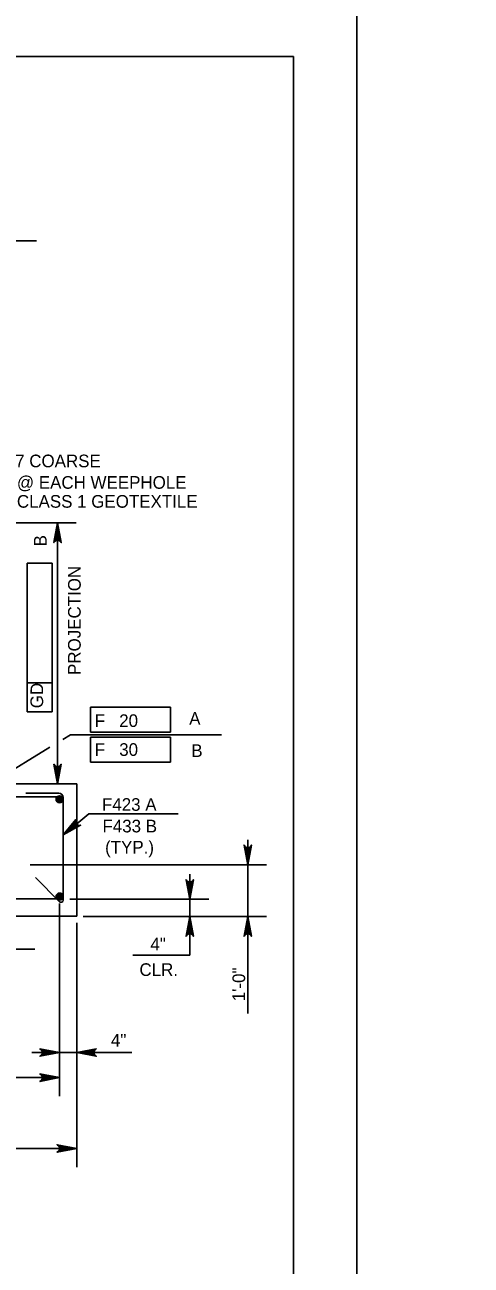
# Model space of a CAD drawing. Extents: x 638340 to 640242, y 295465 to 298435.
# Drawn here: x 639197.8 to 639303.6, y 296352.1 to 296646 of the extents above; entities that cross this region are included whole.
import ezdxf

# ---------------------------------------------------------------- set-up
doc = ezdxf.new("R2010")
doc.units = 0
for name, color, linetype in [('2', 7, 'Continuous'), ('Level 3', 7, 'Continuous'), ('Level 4', 7, 'Continuous'), ('Level 5', 7, 'Continuous'), ('Level 6', 7, 'Continuous'), ('Level 8', 7, 'Continuous'), ('Level 9', 7, 'Continuous'), ('PLT-BNDY', 7, 'Continuous')]:
    doc.layers.add(name, color=color, linetype=linetype)

msp = doc.modelspace()

# ---------------------------------------------------------------- linework, layer by layer
at = {"layer": '2'}
for p, q in [((638475.46, 296638.46), (639261.46, 296638.46)), ((639261.46, 296638.46), (639261.46, 296074.46))]:
    msp.add_line(p, q, dxfattribs=at)
at = {"layer": 'Level 3'}
for p, q in [((639164.96, 296594.81), (639200.6, 296594.81)), ((639250.64, 296449.91), (639250.64, 296452.85)), ((639199.1, 296446.96), (639255.06, 296446.96)), ((639250.64, 296446.96), (639250.64, 296434.69)), ((639236.89, 296441.77), (639236.89, 296444.77)), ((639208.44, 296438.78), (639241.38, 296438.78)), ((639236.89, 296438.78), (639236.89, 296434.69)), ((639211.63, 296434.69), (639255.06, 296434.69)), ((639211.65, 296434.69), (639241.38, 296434.69)), ((639236.89, 296431.69), (639236.89, 296425.53)), ((639250.64, 296431.74), (639250.64, 296411.75)), ((639236.89, 296425.53), (639223.38, 296425.53))]:
    msp.add_line(p, q, dxfattribs=at)
for points in [[(639250.64, 296446.96), (639249.77, 296451.61), (639250.01, 296451.25), (639250.33, 296451.07), (639250.64, 296451.02), (639250.95, 296451.07), (639251.26, 296451.25), (639251.51, 296451.61), (639250.64, 296446.96), (639251.26, 296451.25), (639250.95, 296451.07), (639250.64, 296446.96), (639250.64, 296451.02), (639250.33, 296451.07), (639250.64, 296446.96), (639250.01, 296451.25)], [(639236.89, 296438.78), (639236.02, 296443.43), (639236.27, 296443.07), (639236.58, 296442.89), (639236.89, 296442.83), (639237.2, 296442.89), (639237.51, 296443.07), (639237.76, 296443.43), (639236.89, 296438.78), (639237.51, 296443.07), (639237.2, 296442.89), (639236.89, 296438.78), (639236.89, 296442.83), (639236.58, 296442.89), (639236.89, 296438.78), (639236.27, 296443.07)], [(639236.89, 296434.69), (639237.76, 296430.04), (639237.51, 296430.39), (639237.2, 296430.58), (639236.89, 296430.63), (639236.58, 296430.58), (639236.27, 296430.39), (639236.02, 296430.04), (639236.89, 296434.69), (639236.27, 296430.39), (639236.58, 296430.58), (639236.89, 296434.69), (639236.89, 296430.63), (639237.2, 296430.58), (639236.89, 296434.69), (639237.51, 296430.39)], [(639250.64, 296434.69), (639251.51, 296430.04), (639251.26, 296430.39), (639250.95, 296430.58), (639250.64, 296430.63), (639250.33, 296430.58), (639250.01, 296430.39), (639249.77, 296430.04), (639250.64, 296434.69), (639250.01, 296430.39), (639250.33, 296430.58), (639250.64, 296434.69), (639250.64, 296430.63), (639250.95, 296430.58), (639250.64, 296434.69), (639251.26, 296430.39)]]:
    msp.add_lwpolyline(points, dxfattribs=at)
for points in [[(639250.15, 296449.91), (639251.13, 296449.91), (639250.64, 296446.96)], [(639236.39, 296441.77), (639237.39, 296441.77), (639236.89, 296438.78)], [(639236.39, 296431.69), (639237.39, 296431.69), (639236.89, 296434.69)], [(639250.15, 296431.74), (639251.13, 296431.74), (639250.64, 296434.69)]]:
    msp.add_lwpolyline(points, close=True, dxfattribs=at)
at = {"layer": 'Level 4'}
for p, q in [((639161.27, 296527.93), (639209.99, 296527.93)), ((639205.57, 296466.12), (639205.57, 296527.93)), ((639205.57, 296466.12), (639205.57, 296527.93)), ((639198.37, 296483.21), (639198.37, 296518.44)), ((639198.37, 296518.44), (639204.27, 296518.44)), ((639204.27, 296518.44), (639204.27, 296483.21)), ((639204.27, 296490.04), (639198.37, 296490.04)), ((639204.27, 296483.21), (639198.37, 296483.21)), ((639213.4, 296484.28), (639232.31, 296484.28)), ((639213.4, 296478.38), (639213.4, 296484.28)), ((639232.31, 296484.28), (639232.31, 296478.38)), ((639206.8, 296476.66), (639208.6, 296477.76)), ((639208.6, 296477.76), (639244.39, 296477.76)), ((639232.31, 296478.38), (639213.4, 296478.38)), ((639213.4, 296477.17), (639232.31, 296477.17)), ((639213.4, 296471.28), (639213.4, 296477.17)), ((639232.31, 296477.17), (639232.31, 296471.28)), ((639184.58, 296463.05), (639203.75, 296474.79)), ((639184.58, 296463.05), (639203.75, 296474.79)), ((639232.31, 296471.28), (639213.4, 296471.28)), ((639202.4, 296466.12), (639209.99, 296466.12)), ((639202.4, 296466.12), (639209.99, 296466.12)), ((639202.4, 296466.12), (639209.99, 296466.12)), ((639212.95, 296459.03), (639206.88, 296454.01)), ((639212.95, 296459.03), (639234.15, 296459.03)), ((639206.03, 296437.78), (639206.03, 296392.11)), ((639210.09, 296433.24), (639210.09, 296375.34)), ((639210.09, 296412.96), (639210.09, 296401.49)), ((639206.03, 296402.45), (639199.46, 296402.45)), ((639206.03, 296402.45), (639223.17, 296402.45)), ((639100.09, 296396.53), (639206.03, 296396.53)), ((639096.03, 296379.76), (639210.09, 296379.76))]:
    msp.add_line(p, q, dxfattribs=at)
for points in [[(639205.57, 296527.93), (639206.44, 296523.28), (639206.19, 296523.64), (639205.88, 296523.82), (639205.57, 296523.87), (639205.26, 296523.82), (639204.95, 296523.64), (639204.7, 296523.28), (639205.57, 296527.93), (639204.95, 296523.64), (639205.26, 296523.82), (639205.57, 296527.93), (639205.57, 296523.87), (639205.88, 296523.82), (639205.57, 296527.93), (639206.19, 296523.64)], [(639205.57, 296466.12), (639204.7, 296470.77), (639204.95, 296470.42), (639205.26, 296470.23), (639205.57, 296470.18), (639205.88, 296470.23), (639206.19, 296470.42), (639206.44, 296470.77), (639205.57, 296466.12), (639206.19, 296470.42), (639205.88, 296470.23), (639205.57, 296466.12), (639205.57, 296470.18), (639205.26, 296470.23), (639205.57, 296466.12), (639204.95, 296470.42)], [(639205.57, 296466.12), (639204.7, 296470.77), (639204.95, 296470.42), (639205.26, 296470.23), (639205.57, 296470.18), (639205.88, 296470.23), (639206.19, 296470.42), (639206.44, 296470.77), (639205.57, 296466.12), (639206.19, 296470.42), (639205.88, 296470.23), (639205.57, 296466.12), (639205.57, 296470.18), (639205.26, 296470.23), (639205.57, 296466.12), (639204.95, 296470.42)], [(639206.88, 296454.02), (639209.92, 296457.65), (639209.8, 296457.23), (639209.85, 296456.87), (639210.01, 296456.6), (639210.25, 296456.39), (639210.59, 296456.27), (639211.03, 296456.31), (639206.88, 296454.02), (639210.59, 296456.27), (639210.25, 296456.39), (639206.88, 296454.02), (639210.01, 296456.6), (639209.85, 296456.87), (639206.88, 296454.02), (639209.8, 296457.23)], [(639206.03, 296402.45), (639201.38, 296401.58), (639201.74, 296401.82), (639201.92, 296402.14), (639201.98, 296402.45), (639201.92, 296402.76), (639201.74, 296403.07), (639201.38, 296403.32), (639206.03, 296402.45), (639201.74, 296403.07), (639201.92, 296402.76), (639206.03, 296402.45), (639201.98, 296402.45), (639201.92, 296402.14), (639206.03, 296402.45), (639201.74, 296401.82)], [(639210.09, 296402.45), (639214.74, 296403.32), (639214.38, 296403.07), (639214.2, 296402.76), (639214.14, 296402.45), (639214.2, 296402.14), (639214.38, 296401.82), (639214.74, 296401.58), (639210.09, 296402.45), (639214.38, 296401.82), (639214.2, 296402.14), (639210.09, 296402.45), (639214.14, 296402.45), (639214.2, 296402.76), (639210.09, 296402.45), (639214.38, 296403.07)], [(639206.03, 296396.53), (639201.38, 296395.65), (639201.74, 296395.9), (639201.92, 296396.21), (639201.98, 296396.53), (639201.92, 296396.84), (639201.74, 296397.15), (639201.38, 296397.4), (639206.03, 296396.53), (639201.74, 296397.15), (639201.92, 296396.84), (639206.03, 296396.53), (639201.98, 296396.53), (639201.92, 296396.21), (639206.03, 296396.53), (639201.74, 296395.9)], [(639210.09, 296379.76), (639205.44, 296378.88), (639205.8, 296379.13), (639205.98, 296379.44), (639206.04, 296379.76), (639205.98, 296380.07), (639205.8, 296380.38), (639205.44, 296380.63), (639210.09, 296379.76), (639205.8, 296380.38), (639205.98, 296380.07), (639210.09, 296379.76), (639206.04, 296379.76), (639205.98, 296379.44), (639210.09, 296379.76), (639205.8, 296379.13)]]:
    msp.add_lwpolyline(points, dxfattribs=at)
for points in [[(639205.08, 296524.98), (639206.06, 296524.98), (639205.57, 296527.93)], [(639205.08, 296469.07), (639206.06, 296469.07), (639205.57, 296466.12)], [(639205.08, 296469.07), (639206.06, 296469.07), (639205.57, 296466.12)], [(639202.95, 296401.96), (639202.95, 296402.94), (639205.9, 296402.45)], [(639213.31, 296402.94), (639213.31, 296401.96), (639210.36, 296402.45)], [(639203.09, 296397.02), (639203.09, 296396.04), (639206.03, 296396.53)], [(639207.14, 296380.25), (639207.14, 296379.27), (639210.09, 296379.76)]]:
    msp.add_lwpolyline(points, close=True, dxfattribs=at)
at = {"layer": 'Level 5'}
for p, q in [((639206.1, 296466.11), (639206.1, 296466.11)), ((639206.1, 296466.11), (639206.1, 296466.11)), ((639209.85, 296466.11), (639209.85, 296466.11)), ((639209.85, 296466.11), (639209.85, 296466.11))]:
    msp.add_line(p, q, dxfattribs=at)
at = {"layer": 'Level 6'}
for p, q in [((639206.88, 296463.05), (639099.25, 296463.05)), ((639198.02, 296463.95), (639205.86, 296463.95)), ((639206.88, 296438.57), (639206.88, 296462.92)), ((639200.32, 296443.91), (639206.01, 296438.21)), ((639099.24, 296438.86), (639206.88, 296438.86))]:
    msp.add_line(p, q, dxfattribs=at)
for centre, radius in [((639206.03, 296462.48), 0.832), ((639206.03, 296462.48), 0.624), ((639206.03, 296462.48), 0.416), ((639206.03, 296462.48), 0.208), ((639206.03, 296439.44), 0.832), ((639206.03, 296439.44), 0.624), ((639206.03, 296439.44), 0.416), ((639206.03, 296439.44), 0.208)]:
    msp.add_circle(centre, radius, dxfattribs=at)
for centre, radius, start, end in [((639205.86, 296462.92), 1.02, 0, 90), ((639206.37, 296438.57), 0.511, 225, 0)]:
    msp.add_arc(centre, radius, start, end, dxfattribs=at)
at = {"layer": 'Level 8'}
msp.add_line((639200.19, 296426.97), (639194.06, 296426.97), dxfattribs=at)
at = {"layer": 'Level 9'}
for p, q in [((639210.09, 296466.12), (639156.55, 296466.12)), ((639210.09, 296466.12), (639156.55, 296466.12)), ((639210.09, 296466.12), (639156.55, 296466.12)), ((639210.09, 296434.77), (639210.09, 296466.12)), ((639096.03, 296434.77), (639210.09, 296434.77))]:
    msp.add_line(p, q, dxfattribs=at)
at = {"layer": 'PLT-BNDY'}
for points in [[(638435.46, 296653.46), (639276.46, 296653.46), (639276.46, 296059.46), (638435.46, 296059.46)], [(639276.46, 296653.46), (640117.46, 296653.46), (640117.46, 296059.46), (639276.46, 296059.46)]]:
    msp.add_lwpolyline(points, close=True, dxfattribs=at)

# ---------------------------------------------------------------- texts
at = {"layer": 'Level 3'}
for s, height, p in [('1/2 C.Y. NO. 57 COARSE', 3.0001, (639169.42, 296541.13)), ('4"', 3, (639227.55, 296426.66)), ('CLR.', 3, (639224.96, 296420.62)), ('4"', 3, (639218.2, 296403.9))]:
    msp.add_text(s, height=height, dxfattribs=at).set_placement(p)
msp.add_text('1\'-0"', height=3, rotation=90, dxfattribs=at).set_placement((639250, 296414.63))
at = {"layer": 'Level 4'}
for s, height, p in [('AGGREGATE @ EACH WEEPHOLE', 3.0001, (639169.4, 296536.04)), ('WRAPPED IN CLASS 1 GEOTEXTILE', 3.0001, (639169.4, 296531.55)), ('F   20', 3, (639214.37, 296479.6)), ('A', 3, (639236.75, 296480.13)), ('F   30', 3, (639214.37, 296472.76)), ('B', 3, (639237.25, 296472.5)), ('F423 A', 3, (639216.08, 296459.74)), ('F433 B', 3, (639216.2, 296454.63)), ('(TYP.)', 3, (639216.82, 296449.63))]:
    msp.add_text(s, height=height, dxfattribs=at).set_placement(p)
for s, p in [('B', (639202.97, 296522.39)), ('PROJECTION', (639211.04, 296491.93)), ('GD', (639202.14, 296484.04))]:
    msp.add_text(s, height=3, rotation=90, dxfattribs=at).set_placement(p)

doc.saveas('drawing.dxf')
